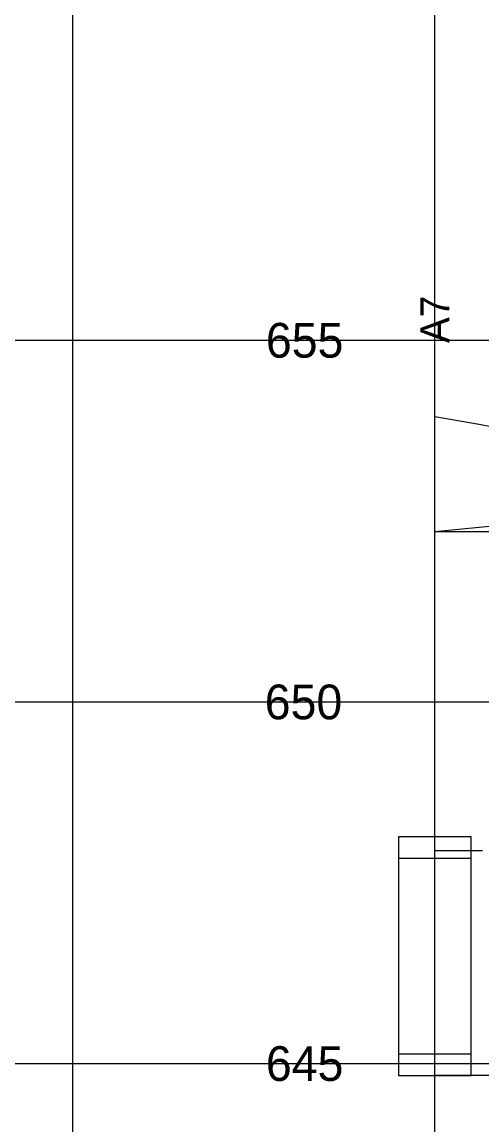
# Model space of a CAD drawing. Extents: x 2252703 to 2264864, y 13787568 to 13790989.
# Drawn here: x 2264585.2 to 2264616.9, y 13788381.5 to 13788457.8 of the extents above; entities that cross this region are included whole.
import ezdxf

# ---------------------------------------------------------------- set-up
doc = ezdxf.new("R2010")
doc.units = 0
for name, color, linetype in [('blank4', 7, 'Continuous'), ('BORD_grid_bottom_major_5int', 7, 'Continuous'), ('D_DRN_PROF_HGL', 7, 'Continuous'), ('D_PROF_1', 7, 'Continuous'), ('D_PROF_NOTES_1', 7, 'Continuous'), ('Default', 7, 'Continuous'), ('Drain_PipeInside', 7, 'Continuous'), ('E_Terrain', 7, 'Continuous'), ('Inlet', 7, 'Continuous'), ('z - Construction', 7, 'Continuous')]:
    doc.layers.add(name, color=color, linetype=linetype)

msp = doc.modelspace()

# ---------------------------------------------------------------- linework, layer by layer
at = {"layer": 'blank4'}
msp.add_lwpolyline([(2264613.672, 13788360.788), (2264613.672, 13788435.788), (2264657.922, 13788435.788), (2264657.922, 13788360.788)], close=True, dxfattribs=at)
at = {"layer": 'BORD_grid_bottom_major_5int'}
for p, q in [((2264588.672, 13788310.788), (2264588.672, 13788610.788)), ((2264613.672, 13788310.788), (2264613.672, 13788610.788)), ((2264413.672, 13788435.788), (2264763.672, 13788435.788)), ((2264413.672, 13788410.788), (2264763.672, 13788410.788)), ((2264413.672, 13788385.788), (2264763.672, 13788385.788))]:
    msp.add_line(p, q, dxfattribs=at)
at = {"layer": 'D_DRN_PROF_HGL'}
msp.add_lwpolyline([(2264613.672, 13788400.522), (2264613.714, 13788400.522), (2264613.757, 13788400.522), (2264613.8, 13788400.522), (2264613.842, 13788400.522), (2264613.885, 13788400.522), (2264613.927, 13788400.522), (2264613.97, 13788400.522), (2264614.013, 13788400.522), (2264614.055, 13788400.522), (2264614.098, 13788400.522), (2264614.141, 13788400.522), (2264614.183, 13788400.522), (2264614.226, 13788400.522), (2264614.269, 13788400.522), (2264614.311, 13788400.522), (2264614.354, 13788400.522), (2264614.396, 13788400.522), (2264614.439, 13788400.522), (2264614.482, 13788400.522), (2264614.524, 13788400.522), (2264614.567, 13788400.522), (2264614.61, 13788400.522), (2264614.652, 13788400.522), (2264614.695, 13788400.522), (2264614.737, 13788400.521), (2264614.78, 13788400.521), (2264614.823, 13788400.521), (2264614.865, 13788400.521), (2264614.908, 13788400.521), (2264614.95, 13788400.521), (2264614.993, 13788400.521), (2264615.036, 13788400.521), (2264615.078, 13788400.521), (2264615.121, 13788400.521), (2264615.163, 13788400.521), (2264615.206, 13788400.521), (2264615.249, 13788400.521), (2264615.291, 13788400.521), (2264615.334, 13788400.521), (2264615.376, 13788400.521), (2264615.419, 13788400.521), (2264615.462, 13788400.521), (2264615.504, 13788400.521), (2264615.547, 13788400.521), (2264615.589, 13788400.521), (2264615.632, 13788400.521), (2264615.675, 13788400.521), (2264615.717, 13788400.521), (2264615.76, 13788400.521), (2264615.802, 13788400.521), (2264615.845, 13788400.521), (2264615.888, 13788400.521), (2264615.93, 13788400.521), (2264615.973, 13788400.521), (2264616.015, 13788400.521), (2264616.058, 13788400.521), (2264616.1, 13788400.52), (2264616.143, 13788400.52), (2264616.186, 13788400.52), (2264616.228, 13788400.52), (2264616.271, 13788400.52), (2264616.313, 13788400.52), (2264616.356, 13788400.52), (2264616.398, 13788400.52), (2264616.441, 13788400.52), (2264616.483, 13788400.52), (2264616.526, 13788400.52), (2264616.569, 13788400.52), (2264616.611, 13788400.52), (2264616.654, 13788400.52), (2264616.696, 13788400.52), (2264616.739, 13788400.52), (2264616.781, 13788400.52), (2264616.824, 13788400.52), (2264616.866, 13788400.52), (2264616.909, 13788400.52), (2264616.952, 13788400.52)], dxfattribs=at)
at = {"layer": 'D_PROF_1'}
msp.add_lwpolyline([(2264613.672, 13788422.562), (2264617.672, 13788422.967), (2264617.672, 13788422.967), (2264624.672, 13788423.675), (2264655.672, 13788420.575), (2264655.901, 13788421.594), (2264656.422, 13788423.908), (2264656.422, 13788423.908), (2264657.922, 13788424.058)], dxfattribs=at)
at = {"layer": 'Drain_PipeInside'}
for points in [[(2264611.172, 13788386.473), (2264616.172, 13788386.473), (2264616.172, 13788401.473), (2264611.172, 13788401.473)], [(2264611.172, 13788384.959), (2264616.172, 13788384.959), (2264616.172, 13788399.959), (2264611.172, 13788399.959)]]:
    msp.add_lwpolyline(points, close=True, dxfattribs=at)
at = {"layer": 'E_Terrain'}
msp.add_lwpolyline([(2264613.672, 13788430.519), (2264616.733, 13788429.991), (2264617.672, 13788429.811), (2264617.672, 13788429.811), (2264623.449, 13788428.698), (2264624.527, 13788427.828), (2264624.606, 13788427.799), (2264626.031, 13788426.981), (2264633.42, 13788421.619), (2264643.69, 13788425.651), (2264645.365, 13788426.099), (2264645.783, 13788425.86), (2264649.676, 13788425.264), (2264656.422, 13788424.521), (2264656.422, 13788424.521), (2264657.922, 13788424.356)], dxfattribs=at)
at = {"layer": 'Inlet'}
msp.add_lwpolyline([(2264613.672, 13788422.575), (2264617.672, 13788422.575), (2264617.672, 13788384.959), (2264613.672, 13788384.959)], close=True, dxfattribs=at)
at = {"layer": 'z - Construction'}
for p, q in [((2264613.672, 13788410.788), (2264657.922, 13788410.788)), ((2264613.672, 13788385.788), (2264657.922, 13788385.788))]:
    msp.add_line(p, q, dxfattribs=at)

# ---------------------------------------------------------------- texts
at = {"layer": 'D_PROF_NOTES_1'}
msp.add_text('A7', height=2, rotation=90, dxfattribs=at).set_placement((2264614.672, 13788435.6))
at = {"layer": 'Default'}
for s, p in [('655', (2264602.004, 13788434.588)), ('650', (2264601.925, 13788409.588)), ('645', (2264602.004, 13788384.588))]:
    msp.add_text(s, height=2.4, dxfattribs=at).set_placement(p)

doc.saveas('drawing.dxf')
